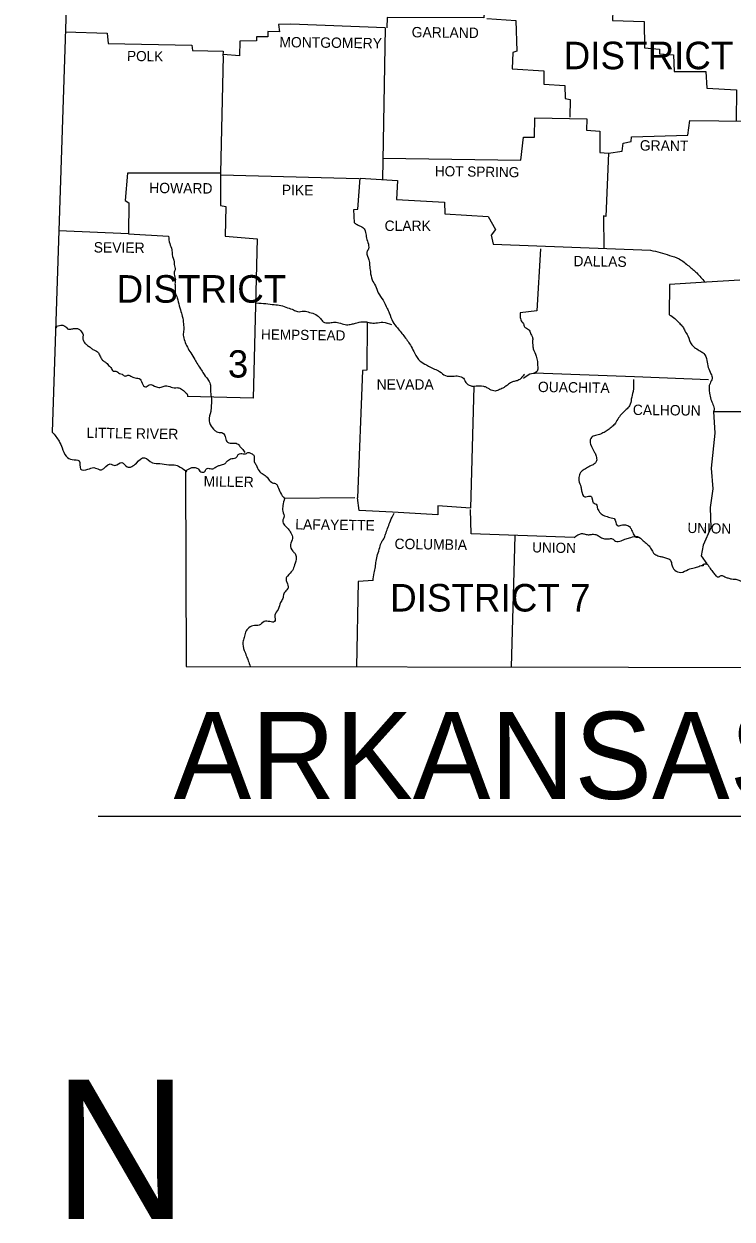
# Model space of a CAD drawing. Extents: x 19118 to 454486, y 1325406 to 1693506.
# Drawn here: x 26405.2 to 26698.5, y 1326547.3 to 1327042.2 of the extents above; entities that cross this region are included whole.
import ezdxf

# ---------------------------------------------------------------- set-up
doc = ezdxf.new("R2010")
doc.units = 0
doc.layers.add('S_CURB', color=7, linetype='Continuous')

msp = doc.modelspace()

# ---------------------------------------------------------------- linework, layer by layer
at = {"layer": 'S_CURB'}
for p, q in [((26554.87, 1327040.58), (26553.7, 1326977.78)), ((26435.93, 1326714.21), (26937.16, 1326714.21))]:
    msp.add_line(p, q, dxfattribs=at)
for points in [[(26405.17, 1327310.68), (26425.87, 1327144.48), (26416.87, 1326873.19)], [(26629.27, 1327056.58), (26596.57, 1327057.58), (26595.67, 1327044.68), (26555.67, 1327044.88), (26555.5, 1327040.56)], [(26638.17, 1327056.88), (26649.37, 1327056.18), (26648.97, 1327043.68), (26662.07, 1327043.18), (26662.27, 1327032.28), (26668.47, 1327031.78), (26668.47, 1327029.88), (26674.27, 1327029.48), (26674.47, 1327022.48), (26687.67, 1327022.48), (26688.07, 1327015.58), (26700.27, 1327014.98), (26700.17, 1327001.98)], [(26515.67, 1327042.23), (26515.67, 1327042.08), (26510.67, 1327041.98), (26511.07, 1327038.98), (26506.27, 1327039.08), (26506.17, 1327036.88), (26501.47, 1327036.88), (26501.57, 1327035.28), (26494.57, 1327035.08), (26494.47, 1327028.98), (26487.67, 1327029.58)], [(26554.87, 1327040.58), (26515.67, 1327042.08)], [(26596.87, 1327044.48), (26608.97, 1327043.58), (26609.37, 1327030.98), (26607.67, 1327030.38), (26607.47, 1327023.68), (26620.57, 1327022.78), (26620.57, 1327017.28), (26629.27, 1327016.78), (26629.37, 1327011.28), (26631.47, 1327010.98), (26631.37, 1327003.58)], [(26422.37, 1327038.98), (26439.67, 1327038.38), (26440.07, 1327034.18), (26474.67, 1327033.48), (26475.07, 1327031.28), (26487.67, 1327030.88), (26487.57, 1327028.98)], [(26487.65, 1327028.81), (26486.57, 1326980.58)], [(26553.87, 1326986.58), (26611.07, 1326985.78), (26612.17, 1326995.28), (26616.67, 1326995.28), (26616.77, 1327003.28), (26638.37, 1327002.98), (26638.17, 1326998.18), (26643.77, 1326997.78), (26643.77, 1326988.98), (26647.37, 1326988.68), (26647.32, 1326987.77)], [(26647.37, 1326988.68), (26652.97, 1326989.48), (26653.37, 1326992.88), (26656.67, 1326993.48), (26656.87, 1326995.48), (26680.17, 1326996.18), (26681.07, 1327002.28), (26704.97, 1327001.88)], [(26647.37, 1326988.68), (26646.17, 1326962.48), (26645.27, 1326962.78), (26645.37, 1326949.18)], [(26486.46, 1326980.39), (26448.07, 1326980.48), (26447.17, 1326969.08), (26448.57, 1326968.08), (26448.47, 1326955.28), (26419.63, 1326956.55)], [(26486.57, 1326980.38), (26486.57, 1326967.08), (26488.77, 1326966.68), (26488.57, 1326954.28), (26501.77, 1326953.28), (26500.17, 1326887.18), (26472.97, 1326887.88)], [(26486.77, 1326979.68), (26543.97, 1326978.18)], [(26542.07, 1326959.88), (26541.87, 1326965.38), (26543.47, 1326965.48), (26544.47, 1326978.38), (26559.87, 1326977.38), (26559.47, 1326969.48), (26579.37, 1326968.38), (26579.47, 1326963.58), (26597.47, 1326962.48), (26600.57, 1326957.08), (26598.67, 1326954.68), (26599.57, 1326950.98), (26664.77, 1326948.58)], [(26448.47, 1326955.28), (26465.07, 1326954.28)], [(26619.17, 1326949.08), (26617.67, 1326923.38), (26610.77, 1326922.58)], [(26687.93, 1326935.23), (26672.57, 1326934.28), (26672.47, 1326921.78)], [(26701.77, 1326936.08), (26687.93, 1326935.23)], [(26547.37, 1326918.78), (26547.17, 1326898.88), (26545.37, 1326898.68), (26543.37, 1326845.99)], [(26418.37, 1326916.18), (26418.77, 1326916.58)], [(26616.67, 1326897.68), (26658.07, 1326896.18), (26688.77, 1326894.98)], [(26591.47, 1326892.08), (26590.17, 1326841.69), (26576.67, 1326842.59), (26576.57, 1326838.89), (26557.9, 1326839.98)], [(26690.77, 1326881.68), (26691.33, 1326872.78), (26689.86, 1326858.3), (26690.49, 1326849.7), (26689.44, 1326841.93), (26689.65, 1326833.54), (26686.51, 1326826.4), (26685.67, 1326822), (26687.98, 1326818.64)], [(26690.77, 1326881.68), (26735.97, 1326881.78)], [(26472.17, 1326857.09), (26472.37, 1326776.19), (26838.86, 1326775.59)], [(26542.25, 1326845.97), (26513.07, 1326845.69)], [(26557.9, 1326839.98), (26544.07, 1326840.79), (26543.37, 1326845.99)], [(26633.07, 1326829.49), (26590.37, 1326831.09), (26590.17, 1326841.19)], [(26608.57, 1326830.19), (26606.99, 1326775.93)], [(26549.77, 1326811.69), (26543.57, 1326811.29), (26542.88, 1326776.05)]]:
    msp.add_lwpolyline(points, dxfattribs=at)
for points in [[(26542.07, 1326959.88), (26543.67, 1326958.88), (26545.57, 1326957.98), (26546.57, 1326956.48), (26546.97, 1326954.18), (26547.67, 1326951.68), (26547.87, 1326949.08), (26547.27, 1326947.68), (26548.07, 1326944.48), (26548.37, 1326942.28), (26548.67, 1326939.68), (26549.47, 1326936.18), (26550.77, 1326933.78), (26551.97, 1326930.88), (26553.97, 1326927.78), (26555.67, 1326924.38), (26556.47, 1326922.58), (26557.97, 1326918.88), (26559.87, 1326916.38), (26562.87, 1326912.58), (26565.57, 1326908.68), (26567.07, 1326905.78), (26569.37, 1326902.58), (26571.97, 1326900.98), (26575.27, 1326899.28), (26577.37, 1326898.28), (26579.77, 1326896.58), (26582.87, 1326896.38), (26585.17, 1326896.38), (26587.27, 1326895.48), (26588.27, 1326893.68), (26590.07, 1326892.48), (26591.47, 1326892.08)], [(26465.07, 1326954.28), (26465.57, 1326951.28), (26466.47, 1326948.68), (26466.57, 1326946.68), (26467.47, 1326943.68), (26467.47, 1326942.58), (26467.77, 1326940.38), (26467.37, 1326939.18), (26467.87, 1326936.78), (26467.77, 1326934.98), (26467.77, 1326933.48), (26467.87, 1326930.98), (26468.67, 1326928.78), (26469.47, 1326925.48), (26469.97, 1326923.78), (26470.77, 1326921.18), (26471.27, 1326917.98), (26471.37, 1326915.58), (26471.17, 1326913.38), (26471.77, 1326910.88), (26472.87, 1326908.38), (26474.27, 1326905.98), (26475.97, 1326903.28), (26477.17, 1326901.18), (26478.67, 1326898.88), (26479.87, 1326896.98), (26481.67, 1326894.58), (26482.47, 1326892.58), (26482.47, 1326889.78), (26482.87, 1326887.18), (26482.77, 1326884.28), (26482.57, 1326881.68), (26481.87, 1326878.09), (26482.37, 1326876.39), (26484.27, 1326873.89), (26485.47, 1326873.19), (26487.57, 1326872.79), (26488.57, 1326871.39), (26489.17, 1326869.29), (26491.27, 1326868.59), (26493.57, 1326868.39), (26494.67, 1326867.19), (26496.17, 1326865.59), (26496.67, 1326864.79)], [(26664.77, 1326948.58), (26672.57, 1326946.38), (26676.57, 1326944.88), (26680.57, 1326941.98), (26683.87, 1326939.08), (26687.17, 1326935.38)], [(26501.57, 1326926.68), (26505.37, 1326926.38), (26508.87, 1326925.98), (26511.57, 1326925.68), (26514.37, 1326924.68), (26516.87, 1326923.78), (26518.47, 1326923.08), (26521.17, 1326923.28), (26523.47, 1326922.78), (26526.07, 1326921.88), (26527.97, 1326920.18), (26529.17, 1326918.88), (26531.47, 1326918.38), (26533.37, 1326918.68), (26535.67, 1326918.48), (26538.27, 1326917.68), (26540.37, 1326917.78), (26542.07, 1326918.18), (26544.07, 1326918.68), (26546.57, 1326918.88), (26548.47, 1326918.48), (26550.97, 1326918.38), (26553.87, 1326918.68), (26557.47, 1326917.68)], [(26610.77, 1326922.58), (26610.77, 1326920.68), (26611.47, 1326918.88), (26612.17, 1326918.08), (26612.47, 1326916.78), (26613.37, 1326916.18), (26614.67, 1326914.98), (26615.37, 1326913.28), (26615.87, 1326912.18), (26615.87, 1326910.78), (26615.97, 1326909.38), (26616.17, 1326907.68), (26617.37, 1326904.68), (26617.67, 1326903.48), (26617.87, 1326902.48), (26617.97, 1326900.78), (26617.97, 1326898.78), (26616.67, 1326897.68)], [(26672.47, 1326921.78), (26674.77, 1326920.28), (26676.67, 1326918.28), (26678.07, 1326916.78), (26678.97, 1326915.08), (26680.17, 1326913.08), (26681.87, 1326909.28), (26683.37, 1326907.98), (26685.47, 1326906.68), (26686.77, 1326905.78), (26688.07, 1326902.88), (26688.67, 1326899.98), (26689.77, 1326897.38), (26690.27, 1326895.38), (26689.37, 1326893.38), (26689.17, 1326889.38), (26689.77, 1326886.68), (26690.57, 1326884.68), (26691.07, 1326882.38), (26690.77, 1326881.68)], [(26418.33, 1326916.89), (26422.17, 1326917.08), (26423.67, 1326915.78), (26424.57, 1326915.88), (26426.17, 1326916.08), (26427.67, 1326915.98), (26428.77, 1326915.08), (26429.67, 1326913.48), (26429.57, 1326911.98), (26429.67, 1326911.38), (26430.37, 1326910.08), (26431.57, 1326909.08), (26432.87, 1326908.08), (26434.07, 1326907.28), (26436.07, 1326905.98), (26436.27, 1326905.58), (26437.07, 1326903.98), (26438.07, 1326902.68), (26439.27, 1326901.88), (26440.57, 1326900.48), (26441.17, 1326899.88), (26442.17, 1326898.48), (26443.27, 1326898.38), (26444.77, 1326897.48), (26445.87, 1326897.18), (26447.07, 1326896.38), (26448.27, 1326896.78), (26449.77, 1326896.18), (26451.77, 1326895.58), (26452.87, 1326895.38), (26454.17, 1326893.48), (26455.47, 1326891.88), (26457.07, 1326892.78), (26460.07, 1326891.88), (26461.97, 1326891.78), (26463.67, 1326892.28), (26464.97, 1326892.18), (26467.37, 1326891.58), (26468.87, 1326891.58), (26470.47, 1326890.98), (26471.97, 1326889.78), (26472.97, 1326888.48), (26472.97, 1326887.88)], [(26612.57, 1326897.18), (26611.47, 1326895.88), (26610.17, 1326894.78), (26608.67, 1326894.28), (26607.27, 1326893.88), (26605.47, 1326892.68), (26604.07, 1326891.68), (26602.17, 1326890.78), (26600.37, 1326890.18), (26598.17, 1326890.88), (26596.97, 1326891.58), (26595.67, 1326892.08), (26591.47, 1326892.08)], [(26612.17, 1326895.58), (26614.77, 1326897.28), (26617.67, 1326897.68)], [(26657.67, 1326894.98), (26657.47, 1326889.98), (26656.77, 1326886.88), (26656.07, 1326884.08), (26654.57, 1326882.48), (26652.97, 1326880.89), (26651.47, 1326879.09), (26650.17, 1326876.89), (26648.87, 1326875.49), (26647.17, 1326874.09), (26645.47, 1326873.09), (26643.57, 1326872.19), (26641.47, 1326871.69), (26639.97, 1326870.59), (26639.87, 1326868.19), (26641.57, 1326864.79), (26642.17, 1326863.19), (26642.37, 1326861.29), (26641.67, 1326860.19), (26640.07, 1326859.29), (26638.17, 1326858.19), (26636.47, 1326857.19), (26635.27, 1326855.49), (26635.07, 1326853.19), (26635.87, 1326850.49), (26636.17, 1326848.89), (26637.47, 1326846.39), (26638.47, 1326846.49), (26640.27, 1326846.39), (26640.47, 1326845.89), (26640.57, 1326845.39), (26640.97, 1326844.09), (26642.47, 1326842.99), (26642.67, 1326841.99), (26643.57, 1326840.09), (26645.07, 1326838.79), (26646.17, 1326838.39), (26648.47, 1326837.69), (26649.67, 1326837.39), (26650.97, 1326834.49), (26652.57, 1326834.59), (26653.77, 1326834.79), (26655.77, 1326834.29), (26656.67, 1326833.09), (26657.57, 1326831.09), (26658.77, 1326829.69), (26659.57, 1326829.69)], [(26416.87, 1326873.19), (26419.77, 1326869.39), (26420.97, 1326866.69), (26422.67, 1326863.19), (26425.17, 1326861.79), (26428.07, 1326861.29), (26428.67, 1326857.89), (26431.67, 1326857.79), (26434.07, 1326858.49), (26437.37, 1326857.59), (26440.87, 1326859.99), (26442.87, 1326859.39), (26445.77, 1326860.59), (26447.97, 1326858.79), (26451.77, 1326860.39), (26455.17, 1326862.59), (26458.37, 1326860.49), (26461.47, 1326860.19), (26465.17, 1326859.69), (26468.07, 1326859.49), (26470.67, 1326858.19), (26472.57, 1326856.89), (26472.17, 1326857.09)], [(26472.17, 1326857.09), (26475.67, 1326858.59), (26477.17, 1326858.09), (26478.47, 1326856.79), (26479.97, 1326856.79), (26480.77, 1326857.99), (26482.27, 1326858.09), (26483.47, 1326857.99), (26484.77, 1326858.79), (26485.87, 1326859.29), (26487.37, 1326859.79), (26488.47, 1326860.19), (26489.47, 1326861.29), (26491.27, 1326862.19), (26493.37, 1326862.89), (26493.97, 1326863.89), (26494.97, 1326864.29), (26496.97, 1326864.19), (26498.27, 1326864.79), (26499.37, 1326864.29), (26500.37, 1326863.59), (26500.57, 1326860.99), (26501.37, 1326859.59), (26502.57, 1326857.09), (26504.27, 1326855.79), (26505.87, 1326854.49), (26506.47, 1326853.69), (26508.17, 1326852.19), (26509.67, 1326851.69), (26510.37, 1326850.59), (26511.47, 1326847.99), (26513.07, 1326845.69)], [(26513.07, 1326845.69), (26512.47, 1326842.79), (26512.37, 1326840.49), (26512.87, 1326837.79), (26512.37, 1326836.49), (26513.17, 1326834.59), (26514.67, 1326833.09), (26515.77, 1326831.49), (26516.47, 1326829.19), (26515.57, 1326826.59), (26516.57, 1326823.89), (26517.47, 1326822.89), (26517.97, 1326821.29), (26517.27, 1326818.19), (26516.37, 1326815.89), (26514.37, 1326813.59), (26513.77, 1326812.49), (26514.07, 1326810.99), (26514.57, 1326808.59), (26514.07, 1326807.89), (26512.77, 1326806.19), (26512.37, 1326804.29), (26511.47, 1326802.69), (26510.47, 1326799.79), (26509.17, 1326797.39), (26508.97, 1326794.69), (26506.97, 1326794.69), (26504.67, 1326794.69), (26502.57, 1326793.19), (26500.67, 1326793.09), (26498.37, 1326792.19), (26496.97, 1326790.29), (26496.47, 1326788.19), (26495.87, 1326786.19), (26496.47, 1326782.79), (26497.37, 1326780.39), (26498.07, 1326778.49), (26498.94, 1326776.14)], [(26549.77, 1326811.69), (26550.27, 1326814.89), (26550.77, 1326817.39), (26551.07, 1326819.79), (26551.67, 1326822.49), (26552.57, 1326825.39), (26553.37, 1326827.79), (26554.47, 1326829.49), (26555.17, 1326831.49), (26556.07, 1326833.89), (26556.97, 1326836.39), (26558.57, 1326839.59)], [(26633.07, 1326829.49), (26634.67, 1326830.59), (26636.17, 1326831.19), (26637.67, 1326830.89), (26639.27, 1326830.69), (26640.67, 1326830.89), (26642.47, 1326830.59), (26643.97, 1326829.69), (26645.67, 1326828.99), (26647.37, 1326828.99), (26648.87, 1326828.99), (26650.17, 1326828.09), (26652.57, 1326828.19), (26654.57, 1326828.99), (26656.57, 1326829.59), (26659.27, 1326829.89), (26661.67, 1326828.19), (26663.37, 1326826.79), (26664.77, 1326825.19), (26665.77, 1326823.39), (26666.87, 1326822.39), (26668.67, 1326821.69), (26670.07, 1326821.39), (26671.77, 1326820.89), (26672.67, 1326820.49), (26673.47, 1326818.59), (26674.77, 1326815.99), (26677.27, 1326815.09), (26680.37, 1326816.29), (26682.87, 1326816.99), (26684.67, 1326817.59), (26685.77, 1326817.99), (26686.77, 1326818.09), (26686.47, 1326818.29), (26687.67, 1326818.59), (26688.77, 1326817.79), (26689.47, 1326816.69), (26690.67, 1326815.09), (26691.77, 1326813.69), (26692.87, 1326813.19), (26693.97, 1326813.79), (26695.47, 1326813.29), (26696.77, 1326812.79), (26698.27, 1326812.39), (26699.57, 1326812.29), (26701.27, 1326811.89), (26702.57, 1326811.19), (26703.77, 1326810.49), (26704.97, 1326809.19), (26706.17, 1326807.19), (26706.57, 1326805.59), (26707.97, 1326803.99), (26709.27, 1326803.99), (26711.17, 1326801.39), (26711.87, 1326800.39), (26713.37, 1326798.59), (26714.47, 1326798.59), (26716.57, 1326798.19)]]:
    msp.add_spline(points, degree=3, dxfattribs=at)

# ---------------------------------------------------------------- texts
for s, height, rotation, p in [('GARLAND', 4.301, 359.3658, (26565.77, 1327036.68)), ('MONTGOMERY', 4.301, 359.2944, (26510.97, 1327032.58)), ('POLK', 4.199, 359.2152, (26447.87, 1327026.88)), ('GRANT', 4.301, 359.4032, (26660.27, 1326989.78)), ('HOT SPRING', 4.201, 359.2216, (26575.37, 1326979.18)), ('HOWARD', 4.301, 359.5145, (26457.07, 1326972.18)), ('PIKE', 4.299, 359.0452, (26511.97, 1326971.38)), ('SEVIER', 4.301, 359.4271, (26434.07, 1326947.58)), ('DALLAS', 4.3, 359.2462, (26632.77, 1326941.88)), ('HEMPSTEAD', 4.199, 359.1885, (26503.37, 1326911.58)), ('OUACHITA', 4.301, 359.2043, (26618.07, 1326889.78)), ('CALHOUN', 4.301, 359.3634, (26657.37, 1326880.29)), ('LITTLE RIVER', 4.3007, 359.1697, (26431.07, 1326870.79)), ('MILLER', 4.3, 359.1319, (26479.57, 1326850.69)), ('LAFAYETTE', 4.299, 359.1839, (26517.57, 1326832.89)), ('UNION', 4.201, 358.9456, (26679.99, 1326831.43)), ('COLUMBIA', 4.3, 359.2125, (26558.67, 1326824.79)), ('UNION', 4.201, 358.9584, (26615.67, 1326823.39))]:
    msp.add_text(s, height=height, rotation=rotation, dxfattribs=at).set_placement(p)
for s, height, p in [('DISTRICT 6', 11.4, (26628.75, 1327023.45)), ('CLARK', 4.3, (26554.57, 1326956.48)), ('DISTRICT', 11.4, (26443.57, 1326926.78)), ('3', 11.3, (26489.67, 1326895.78)), ('NEVADA', 4.3, (26551.27, 1326890.78)), ('DISTRICT 7', 11.4, (26556.87, 1326798.89)), ('ARKANSAS HWY. DIST. 9', 36.036, (26467.18, 1326721.3)), ('N', 57.69, (26417.37, 1326547.29))]:
    msp.add_text(s, height=height, dxfattribs=at).set_placement(p)

doc.saveas('drawing.dxf')
